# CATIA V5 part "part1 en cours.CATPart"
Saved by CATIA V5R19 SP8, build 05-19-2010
Part number: part1
Bounding box of the stored display mesh (mm): x 0 to 90, y -158.741 to 441.259, z -663.015 to -168.015
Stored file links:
  G:\EU_thinkMotion\CFAO_2010\SIL_groupe2\SIL_groupe2\A reprendre\fnongaibaa\fnongaibaa\part1 en cours.CATPart
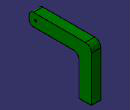
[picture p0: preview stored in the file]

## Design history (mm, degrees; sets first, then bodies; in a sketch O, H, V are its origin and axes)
Body1 (main body)
  Sketch1 on yz-plane, origin (0, 0, 0), H (0, 1, 0), V (0, 0, 1)
    line L1 (321.2594, -663.0146) -> (441.2594, -663.0146)
    line L2 (441.2594, -663.0146) -> (441.2594, -228.0146)
    point P3 (313.939, -283.5067)
    point P4 (-158.7406, -168.0146)
    line L3 (321.2594, -343.0146) -> (321.2594, -663.0146)
    line L4 (266.2594, -288.0146) -> (-118.7406, -288.0146)
    point P5 (-158.7406, -288.0146)
    line L5 (-158.7406, -248.0146) -> (-158.7406, -208.0146)
    line L6 (381.2594, -168.0146) -> (-118.7406, -168.0146)
    arc A1 centre (266.2594, -343.0146) radius 55 from (321.2594, -343.0146) to (266.2594, -288.0146) ccw
    arc A2 centre (381.2594, -228.0146) radius 60 from (381.2594, -168.0146) to (441.2594, -228.0146) cw
    arc A3 centre (-118.7406, -208.0146) radius 40 from (-118.7406, -168.0146) to (-158.7406, -208.0146) ccw
    arc A4 centre (-118.7406, -248.0146) radius 40 from (-118.7406, -288.0146) to (-158.7406, -248.0146) cw
    length L1 = 120
    distance L1 L6 = 495
    radius A1 = 55
    radius A2 = 60
    distance P5 P4 = 120
    radius A3 = 40
    radius A4 = 40
    length L4 = 385
    horizontal: L1 H, L4 H, L6 H
    vertical: L2 V, L3 V, L5 V
    tangency: A1 L3, A1 L4, A2 L6, A2 L2, A3 L6, A3 L5, A4 L4, A4 L5
    coincidence: L6 P4, L5 P4, L4 P5, L5 P5
  Pad1: profile Sketch1, direction (1, 0, 0), length 90
  Sketch2 on face of Pad1 from Sketch1.L1, origin (0, 0, -663.0146), H (1, 0, 0), V (0, -1, 0)
    line L1 (5, -326.2594) -> (85, -326.2594)
    line L2 (85, -326.2594) -> (85, -436.2594)
    line L3 (85, -436.2594) -> (5, -436.2594)
    line L4 (5, -436.2594) -> (5, -326.2594)
    reference projected line E1 (0, -321.2594) -> (20, -321.2594) from edge [face of Pad1 from Sketch1.L1 | face of Pad1 from Sketch1.L3]
    reference projected line E2 (0, -441.2594) -> (20, -441.2594) from edge [face of Pad1 from Sketch1.L2 | face of Pad1 from Sketch1.L1]
    reference projected line E3 (90, -79.4781) -> (90, -99.4781) from edge [face of Pad1 from Sketch1.L1 | end face of Pad1]
    reference projected line E4 (0, -79.4781) -> (0, -99.4781) from edge [start face of Pad1 | face of Pad1 from Sketch1.L1]
    distance L1 E1 = 5
    distance L3 E2 = 5
    distance L2 E3 = 5
    distance L4 E4 = 5
    horizontal: L1 H, L3 H
    vertical: L2 V, L4 V
  Pocket1: profile Sketch2, direction (0, 0, 1), length 400
  Sketch3 on start face of Pad1, origin (0, -93.9369, -243.8314), H (0, 1, 0), V (0, 0, -1)
    point P1 (-4.8037, -15.8168)
    axis line L1 (871.5351, -15.8168) -> (-470.8508, -15.8168)
    reference projected line E1 (-24.8037, 44.1832) -> (360.1963, 44.1832) from edge [start face of Pad1 | face of Pad1 from Sketch1.L4]
    reference projected line E2 (475.1963, -75.8168) -> (-24.8037, -75.8168) from edge [start face of Pad1 | face of Pad1 from Sketch1.L6]
    reference projected line E3 (-64.8037, -35.8168) -> (-64.8037, 4.1832) from edge [start face of Pad1 | face of Pad1 from Sketch1.L5]
    distance P1 E3 = 60
    symmetry: E1 E2 L1
    coincidence: P1 L1
  Hole1: placed by Sketch3, at (0, -98.7406, -228.0146) direction (1, 0, 0), diameter 20, through (limit type 6)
